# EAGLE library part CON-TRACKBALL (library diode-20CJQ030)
Various FFC/FPC connectors for the ITT 8mm trackball with 11pins. - AVX - Molex Please send any comments to: messi@users.sourceforge.net
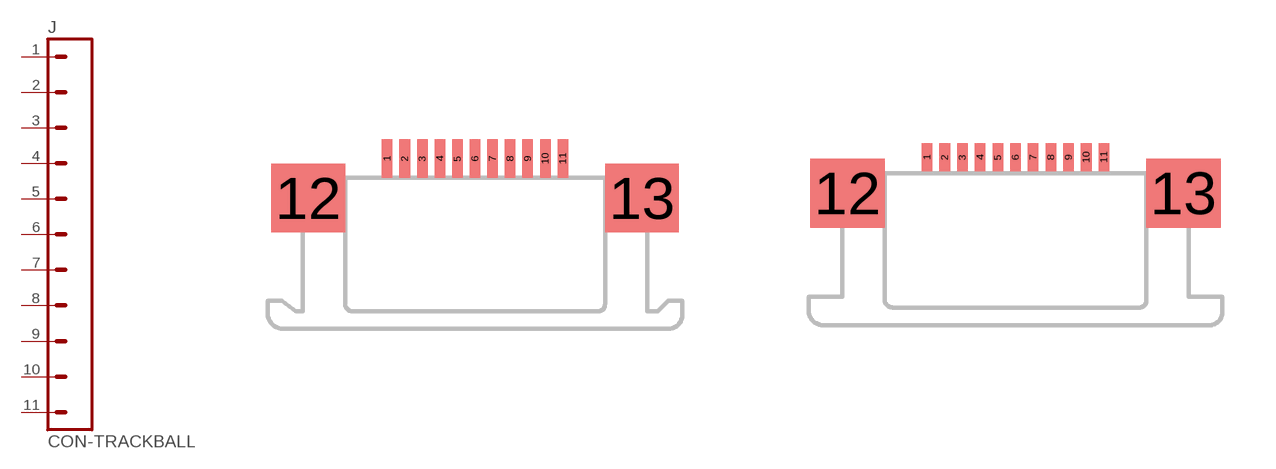
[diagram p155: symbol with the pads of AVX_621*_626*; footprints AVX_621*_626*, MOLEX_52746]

Designator prefix J

## CON-TRACKBALL-1  [AVX_621*_626*]
1  1  pas
2  2  pas
3  3  pas
4  4  pas
5  5  pas
6  6  pas
7  7  pas
8  8  pas
9  9  pas
10  10  pas
11  11  pas

## CON-TRACKBALL-2  [MOLEX_52746]
Pads as for AVX_621*_626*

## CON-TRACKBALL-3  [MOLEX_52893]
Pads as for AVX_621*_626*

## Footprint AVX_621*_626* (pad centres in mm)
AVX 0.50mm Pitch Series (6210/6260 Bottom Contact Type) and (6212/6262 Top Contact Type) ZIF Right Angle SMT Specifications: Number of Contacts from 5 to 40 2000 Connectors per Tape & Reel Voltage -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
smd 0.3 x 1.1: 1 -2.5,0.55; 2 -2,0.55; 3 -1.5,0.55; 4 -1,0.55; 5 -0.5,0.55; 6 0,0.55; 7 0.5,0.55; 8 1,0.55; 9 1.5,0.55; 10 2,0.55; 11 2.5,0.55
smd 2.1 x 1.95: 12 -4.75,-0.575; 13 4.75,-0.575

## Footprint MOLEX_52746 (pad centres in mm)
Molex 0.5 FPC Connector ZIF for SMT (Bottom contact) SD-52746-**17 Please send any comments to: messi@users.sourceforge.net
smd 0.3 x 0.8: 1 -2.5,0.45; 2 -2,0.45; 3 -1.5,0.45; 4 -1,0.45; 5 -0.5,0.45; 6 0,0.45; 7 0.5,0.45; 8 1,0.45; 9 1.5,0.45; 10 2,0.45; 11 2.5,0.45
smd 2.1 x 1.95: 12 -4.75,-0.575; 13 4.75,-0.575

## Footprint MOLEX_52893 (pad centres in mm)
Molex 0.5 FPC Connector ZIF for SMT (Bottom contact) SD-52893-**17 Please send any comments to: messi@users.sourceforge.net
smd 0.3 x 1.4: 1 -2.5,0.7; 2 -2,0.7; 3 -1.5,0.7; 4 -1,0.7; 5 -0.5,0.7; 6 0,0.7; 7 0.5,0.7; 8 1,0.7; 9 1.5,0.7; 10 2,0.7; 11 2.5,0.7
smd 1.6 x 2.2: 12 -5.15,-2.45; 13 5.15,-2.45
